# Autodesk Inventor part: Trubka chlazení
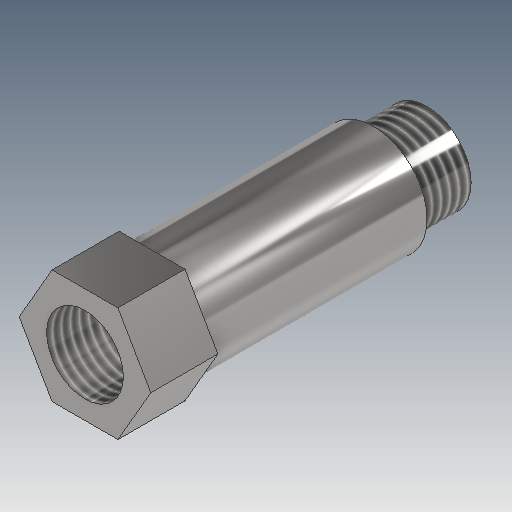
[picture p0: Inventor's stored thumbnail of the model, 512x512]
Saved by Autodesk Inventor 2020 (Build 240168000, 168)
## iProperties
Created: 2025-03
Part Number: Trubka chlazení
Material: Ocel
Document SubType Name: Modeling
Designer: doma
Density: 7.85 g/cm^3
Appearance: Ocel – leštěná
Mass: 54.9894 g
Surface Area: 43.7276 cm^2
Volume: 7.00501 cm^3
Author: doma
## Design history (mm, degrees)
sketch "Náčrt1"
  geometry: C1 r 8 at (0, 0); C2 r 4 at (0, 0); 1 further point
  constraints: 2 centre point, 2 coincident
  dimensions: "d0" = 16 diameter of C1; "d1" = 8 diameter of C2
extrude "Vysunutí1" new body sketch "Náčrt1" distance "d2" = 41; taper "d3" = 0 deg
sketch "Náčrt2"
  geometry: L1 (4.907, 8.5)-(9.815, 0); L2 (9.815, 0)-(4.907, -8.5); L3 (4.907, -8.5)-(-4.907, -8.5); L4 (-4.907, -8.5)-(-9.815, 0); L5 (-9.815, 0)-(-4.907, 8.5); L6 (-4.907, 8.5)-(4.907, 8.5); 2 further points
  constraints: 12 end point, 1 coincident, 13 other
  dimensions: "d4" = 17 distance between parallel lines of L3 L6
extrude "Vysunutí2" join sketch "Náčrt2" distance "d5" = 10; taper "d6" = 0 deg
extrude "Vysunutí3" cut sketch "Náčrt1" extent not by distance; stored distance "d7" = 45; taper "d8" = 0 deg
sketch "Náčrt4"
  geometry: C1 r 6.579 at (0, 0); C2 r 8 at (0, 0) reference; 1 further point
  constraints: 1 centre point, 1 coincident
  dimensions: "d10" = 13.157 diameter of C1
extrude "Vysunutí4" cut sketch "Náčrt4" distance "d11" = 8; taper "d12" = 0 deg
sketch "Náčrt5"
  geometry: 2 further points
hole "Díra1" sketch "Náčrt5" at (0, 0) diameter "d15" = 11.445; stored, may be unused: countersink angle "d19" = 90 deg, drill point angle "d21" = 118 deg; dims "d16" = 8, "d17" = 4, "d18" = 2, "d20" = 12
feature "Závit2" dims "d22" = 18, "d23" = 0
node "Těleso1"
